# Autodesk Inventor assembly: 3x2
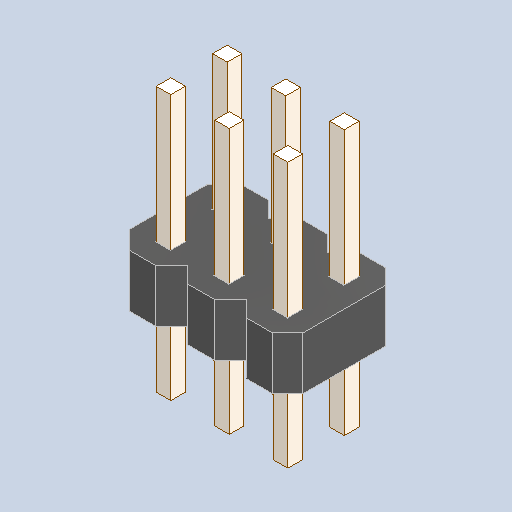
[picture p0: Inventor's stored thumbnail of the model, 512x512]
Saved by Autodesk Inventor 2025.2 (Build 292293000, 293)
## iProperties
Created: 2025-04
Part Number: 3x2
Description: PART--DESC
Document SubType Name: Assembly
Designer: BennF
Author: BennF
Revision Number: NONE
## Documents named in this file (3)
- C:\Users\BennF\Nextcloud\Benutzer\CNC JarBeRi\existing parts\Electronics\RepRap A4988 Shied (USE WITHOUT ARDUINO)\reprap-a4988-1.snapshot.1\RepRap\RepRap\3x2_2.iam
- C:\Users\BennF\Nextcloud\Benutzer\CNC JarBeRi\existing parts\Electronics\RepRap A4988 Shied (USE WITHOUT ARDUINO)\reprap-a4988-1.snapshot.1\RepRap\RepRap\3x2 Geometry.ipt
- C:\Users\BennF\Nextcloud\Benutzer\CNC JarBeRi\existing parts\Electronics\RepRap A4988 Shied (USE WITHOUT ARDUINO)\reprap-a4988-1.snapshot.1\RepRap\RepRap\pin10.ipt
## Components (2 placed, 2 different names)
1. 3x2 Geometry
2. pin10
